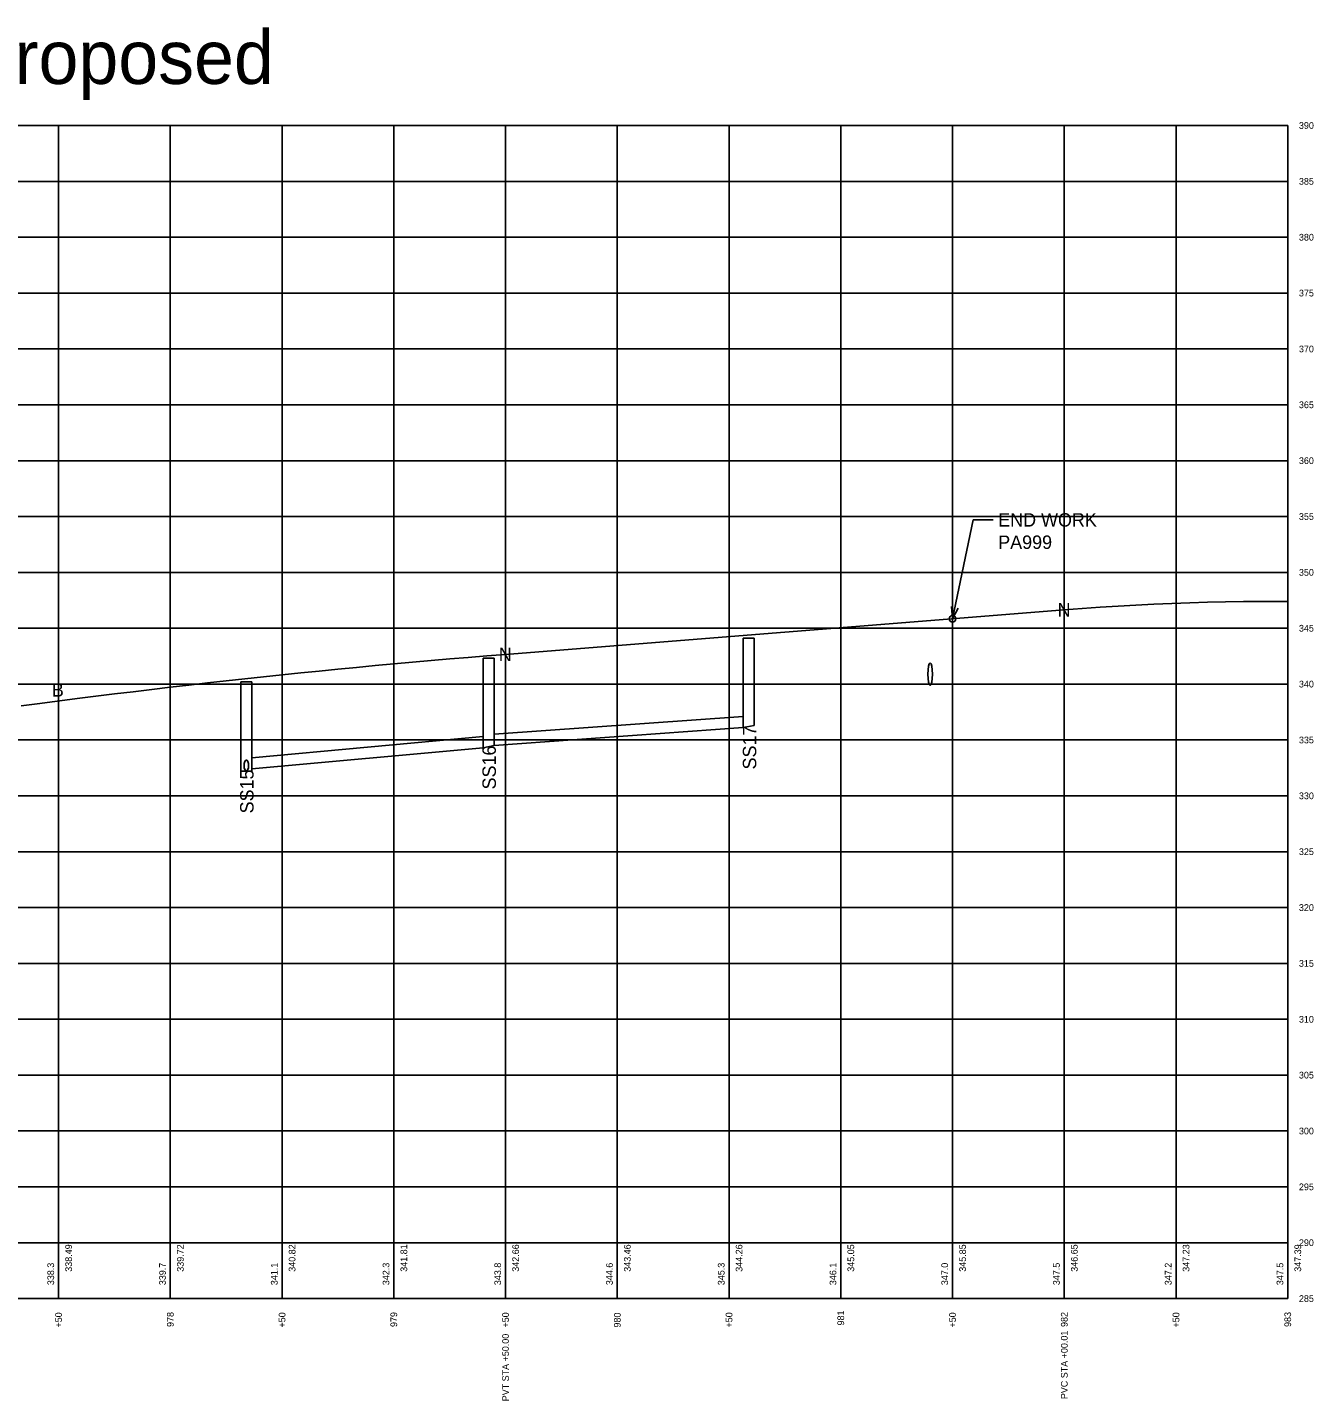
# Model space of a CAD drawing. Extents: x 4987 to 6162, y 4954 to 5569.
# Drawn here: x 5586 to 6162, y 4954 to 5569 of the extents above; entities that cross this region are included whole.
import ezdxf

# ---------------------------------------------------------------- set-up
doc = ezdxf.new("R2010")
doc.units = 0
for name, color, linetype in [('1', 7, 'Continuous'), ('15', 7, 'Continuous'), ('18', 7, 'Continuous'), ('3', 7, 'Continuous'), ('33', 7, 'Continuous'), ('39', 7, 'Continuous'), ('61', 7, 'Continuous'), ('63', 7, 'Continuous')]:
    doc.layers.add(name, color=color, linetype=linetype)

msp = doc.modelspace()

# ---------------------------------------------------------------- linework, layer by layer
at = {"layer": '1'}
for p, q in [((5000, 5000), (6150, 5000)), ((5600, 5000), (5600, 5000)), ((5650, 5000), (5650, 5000)), ((5700, 5000), (5700, 5000)), ((5750, 5000), (5750, 5000)), ((5800, 5000), (5800, 5000)), ((5850, 5000), (5850, 5000)), ((5900, 5000), (5900, 5000)), ((5950, 5000), (5950, 5000)), ((6000, 5000), (6000, 5000)), ((6050, 5000), (6050, 5000)), ((6100, 5000), (6100, 5000)), ((6150, 5000), (6150, 5000))]:
    msp.add_line(p, q, dxfattribs=at)
for points in [[(6050.01, 5308.23), (6050.01, 5000), (6050.01, 5000), (6050.01, 5000)], [(5800, 5288.32), (5800, 5000), (5800, 5000), (5800, 5000)], [(5600, 5000), (5600, 5035)], [(5600, 5000), (5600, 5035)], [(5600, 5000), (5600, 5035)], [(5650, 5000), (5650, 5035)], [(5650, 5000), (5650, 5035)], [(5650, 5000), (5650, 5035)], [(5700, 5000), (5700, 5035)], [(5700, 5000), (5700, 5035)], [(5700, 5000), (5700, 5035)], [(5750, 5000), (5750, 5035)], [(5750, 5000), (5750, 5035)], [(5750, 5000), (5750, 5035)], [(5800, 5000), (5800, 5035)], [(5800, 5000), (5800, 5035)], [(5800, 5000), (5800, 5035)], [(5850, 5000), (5850, 5035)], [(5850, 5000), (5850, 5035)], [(5850, 5000), (5850, 5035)], [(5900, 5000), (5900, 5035)], [(5900, 5000), (5900, 5035)], [(5900, 5000), (5900, 5035)], [(5950, 5000), (5950, 5035)], [(5950, 5000), (5950, 5035)], [(5950, 5000), (5950, 5035)], [(6000, 5000), (6000, 5035)], [(6000, 5000), (6000, 5035)], [(6000, 5000), (6000, 5035)], [(6050, 5000), (6050, 5035)], [(6050, 5000), (6050, 5035)], [(6050, 5000), (6050, 5035)], [(6050.01, 5000), (6050.01, 5035)], [(6100, 5000), (6100, 5035)], [(6100, 5000), (6100, 5035)], [(6100, 5000), (6100, 5035)], [(6150, 5000), (6150, 5035)], [(6150, 5000), (6150, 5035)], [(6150, 5000), (6150, 5035)]]:
    msp.add_lwpolyline(points, dxfattribs=at)
at = {"layer": '15'}
msp.add_circle((6000, 5304.25), 1.5, dxfattribs=at)
at = {"layer": '18'}
for p, q in [((6009.2, 5348.5), (6000, 5304.25)), ((6018.2, 5348.5), (6009.2, 5348.5)), ((5906.29, 5295.55), (5906.29, 5255.55)), ((5906.29, 5295.55), (5911.29, 5295.55)), ((5906.29, 5295.55), (5911.29, 5295.55)), ((5911.29, 5256.55), (5911.29, 5295.55)), ((5789.96, 5286.55), (5789.96, 5246.55)), ((5789.96, 5286.55), (5794.96, 5286.55)), ((5794.96, 5247.55), (5794.96, 5286.55)), ((5794.96, 5256.55), (5794.96, 5286.55)), ((5681.5, 5276.08), (5681.5, 5236.08)), ((5681.5, 5276.08), (5686.5, 5276.08)), ((5686.5, 5236.08), (5686.5, 5276.08)), ((5794.96, 5252.55), (5906.29, 5260.55)), ((5794.96, 5247.55), (5906.29, 5255.55)), ((5906.29, 5255.55), (5911.29, 5256.55)), ((5686.5, 5242.08), (5789.96, 5251.55)), ((5686.5, 5237.08), (5789.96, 5246.55)), ((5789.96, 5246.55), (5794.96, 5247.55)), ((5681.5, 5236.08), (5686.5, 5236.08))]:
    msp.add_line(p, q, dxfattribs=at)
msp.add_lwpolyline([(6002.53, 5309.06), (6000, 5304.25), (5999.6, 5309.67)], dxfattribs=at)
for centre, major_axis, ratio in [((5990, 5279.45), (0, 5), 0.2), ((5684.01, 5238.57), (0, 2.5), 0.4)]:
    msp.add_ellipse(centre, major_axis=major_axis, ratio=ratio, dxfattribs=at)
at = {"layer": '39'}
msp.add_line((5800, 5288.32), (6050.01, 5308.23), dxfattribs=at)
for points in [[(6050.01, 5308.23), (6058.03, 5308.84), (6066.04, 5309.4), (6074.06, 5309.9), (6082.07, 5310.35), (6090.09, 5310.74), (6098.11, 5311.08), (6106.12, 5311.37), (6114.14, 5311.6), (6122.16, 5311.78), (6130.17, 5311.9), (6138.19, 5311.97), (6146.2, 5311.98), (6150, 5311.96)], [(5583.33, 5265.26), (5591.67, 5266.36), (5608.33, 5268.51), (5616.67, 5269.56), (5625, 5270.6), (5633.33, 5271.61), (5641.67, 5272.61), (5650, 5273.59), (5658.33, 5274.56), (5666.67, 5275.51), (5675, 5276.44), (5683.33, 5277.35), (5691.67, 5278.25), (5700, 5279.12), (5708.33, 5279.99), (5716.67, 5280.83), (5725, 5281.66), (5733.33, 5282.47), (5741.67, 5283.26), (5750, 5284.03), (5758.33, 5284.79), (5766.67, 5285.53), (5775, 5286.26), (5783.33, 5286.96), (5791.67, 5287.65), (5800, 5288.32)]]:
    msp.add_lwpolyline(points, dxfattribs=at)
at = {"layer": '63'}
for p, q in [((5000, 5525), (6150, 5525)), ((5000, 5525), (6150, 5525)), ((5600, 5000), (5600, 5525)), ((5650, 5000), (5650, 5525)), ((5700, 5000), (5700, 5525)), ((5750, 5000), (5750, 5525)), ((5800, 5000), (5800, 5525)), ((5850, 5000), (5850, 5525)), ((5900, 5000), (5900, 5525)), ((5950, 5000), (5950, 5525)), ((6000, 5000), (6000, 5525)), ((6050, 5000), (6050, 5525)), ((6100, 5000), (6100, 5525)), ((6150, 5000), (6150, 5525)), ((6150, 5525), (6150, 5525)), ((6150, 5525), (6150, 5525)), ((5000, 5500), (6150, 5500)), ((6150, 5500), (6150, 5500)), ((5000, 5475), (6150, 5475)), ((6150, 5475), (6150, 5475)), ((5000, 5450), (6150, 5450)), ((6150, 5450), (6150, 5450)), ((5000, 5425), (6150, 5425)), ((6150, 5425), (6150, 5425)), ((5000, 5400), (6150, 5400)), ((6150, 5400), (6150, 5400)), ((5000, 5375), (6150, 5375)), ((6150, 5375), (6150, 5375)), ((5000, 5350), (6150, 5350)), ((6150, 5350), (6150, 5350)), ((5000, 5325), (6150, 5325)), ((6150, 5325), (6150, 5325)), ((5000, 5300), (6150, 5300)), ((6150, 5300), (6150, 5300)), ((5000, 5275), (6150, 5275)), ((6150, 5275), (6150, 5275)), ((5000, 5250), (6150, 5250)), ((6150, 5250), (6150, 5250)), ((5000, 5225), (6150, 5225)), ((6150, 5225), (6150, 5225)), ((5000, 5200), (6150, 5200)), ((6150, 5200), (6150, 5200)), ((5000, 5175), (6150, 5175)), ((6150, 5175), (6150, 5175)), ((5000, 5150), (6150, 5150)), ((6150, 5150), (6150, 5150)), ((5000, 5125), (6150, 5125)), ((6150, 5125), (6150, 5125)), ((5000, 5100), (6150, 5100)), ((6150, 5100), (6150, 5100)), ((5000, 5075), (6150, 5075)), ((6150, 5075), (6150, 5075)), ((5000, 5050), (6150, 5050)), ((6150, 5050), (6150, 5050)), ((5000, 5025), (6150, 5025)), ((6150, 5025), (6150, 5025)), ((6150, 5000), (6150, 5000))]:
    msp.add_line(p, q, dxfattribs=at)

# ---------------------------------------------------------------- texts
at = {"layer": '1'}
msp.add_text('PA999 - Proposed', height=24, dxfattribs=at).set_placement((5434.05, 5543.6))
at = {"layer": '18'}
for s, p in [('END WORK', (6020.45, 5345.5)), ('PA999', (6020.45, 5335.5))]:
    msp.add_text(s, height=6, dxfattribs=at).set_placement(p)
for s, p in [('SS17', (5912.18, 5236.81)), ('SS16', (5795.67, 5227.86)), ('SS15', (5687.24, 5217.14))]:
    msp.add_text(s, height=6, rotation=90, dxfattribs=at).set_placement(p)
at = {"layer": '3'}
for s, p in [('338.3', (5598, 5006)), ('339.7', (5648, 5006)), ('341.1', (5698, 5006)), ('342.3', (5748, 5006)), ('343.8', (5798, 5006)), ('344.6', (5848, 5006)), ('345.3', (5898, 5006)), ('346.1', (5948, 5006)), ('347.0', (5998, 5006)), ('347.5', (6048, 5006)), ('347.2', (6098, 5006)), ('347.5', (6148, 5006))]:
    msp.add_text(s, height=3, rotation=90, dxfattribs=at).set_placement(p)
at = {"layer": '33'}
for s, p in [('338.49', (5606, 5012)), ('339.72', (5656, 5012)), ('340.82', (5706, 5012)), ('341.81', (5756, 5012)), ('342.66', (5806, 5012)), ('343.46', (5856, 5012)), ('344.26', (5906, 5012)), ('345.05', (5956, 5012)), ('345.85', (6006, 5012)), ('346.65', (6056, 5012)), ('347.23', (6106, 5012)), ('347.39', (6156, 5012)), ('+50', (5601.5, 4987.04)), ('978', (5651.5, 4987.3)), ('+50', (5701.5, 4987.04)), ('979', (5751.5, 4987.28)), ('+50', (5801.5, 4987.04)), ('980', (5851.5, 4987.04)), ('+50', (5901.5, 4987.04)), ('981', (5951.5, 4987.98)), ('+50', (6001.5, 4987.04)), ('982', (6051.5, 4987.3)), ('+50', (6101.5, 4987.04)), ('983', (6151.5, 4987.3)), ('PVT STA +50.00', (5801.5, 4954.04)), ('PVC STA +00.01', (6051.51, 4954.98))]:
    msp.add_text(s, height=3, rotation=90, dxfattribs=at).set_placement(p)
at = {"layer": '61'}
for s, p in [('N', (6047.01, 5305.23)), ('N', (5797, 5285.32)), ('B', (5597, 5269.4))]:
    msp.add_text(s, height=6, dxfattribs=at).set_placement(p)
at = {"layer": '63'}
for s, p in [('390', (6155, 5523.5)), ('390', (6155, 5523.5)), ('385', (6155, 5498.5)), ('380', (6155, 5473.5)), ('375', (6155, 5448.5)), ('370', (6155, 5423.5)), ('365', (6155, 5398.5)), ('360', (6155, 5373.5)), ('355', (6155, 5348.5)), ('350', (6155, 5323.5)), ('345', (6155, 5298.5)), ('340', (6155, 5273.5)), ('335', (6155, 5248.5)), ('330', (6155, 5223.5)), ('325', (6155, 5198.5)), ('320', (6155, 5173.5)), ('315', (6155, 5148.5)), ('310', (6155, 5123.5)), ('305', (6155, 5098.5)), ('300', (6155, 5073.5)), ('295', (6155, 5048.5)), ('290', (6155, 5023.5)), ('285', (6155, 4998.5))]:
    msp.add_text(s, height=3, dxfattribs=at).set_placement(p)

doc.saveas('drawing.dxf')
